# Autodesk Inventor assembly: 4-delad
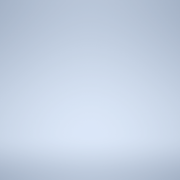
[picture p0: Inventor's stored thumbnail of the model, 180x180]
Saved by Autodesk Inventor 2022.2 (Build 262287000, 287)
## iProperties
RuleStatus: InUse
Created: 2019-06
Part Number: 4-delad
Document SubType Name: Assembly
Designer: cl
Daghöjd: 4000,000 mm
BladBredd: 987,500 mm
Fönsterbredd: 480,000 mm
Fönsterhöjd: 862,000 mm
Brösthöjd: 1070,000 mm
DagBredd: 4000,000 mm
AntalBlad: 4,000 ul
Blad2: 1012,500 mm
Blad3: 0,000 mm
Blad4: 0,000 mm
Blad5: 1012,500 mm
Blad6: 2025,000 mm
MGJ2Djup: 0,000 mm
MGJ2Bredd: 5012,500 mm
MGJ12Djup: 0,000 mm
MGJ12Bredd: 0,000 mm
MGJ56Djup: 0,000 mm
MGJ56Bredd: 0,000 mm
MGJ23Djup: 48,000 mm
MGJ23Bredd: 100,000 mm
MGJ45Djup: 48,000 mm
MGJ45Bredd: 100,000 mm
GarageRegel5: 0,000 mm
GarageRegel6: 0,000 mm
StyrskenaV: 4150,000 mm
Styrrulle2Höjd: 10,000 mm
Styrrulle2Djup: 0,000 mm
FönsterhöjdStyrning: 862,000 mm
BrösthöjdStyrning: 1070,000 mm
FönsterKarm: 54,000 mm
AndraGlasraden: 0,000 mm
BrösthöjdStyrning2: 0,000 mm
InfälldGångDörr: 0,000 ul
Infälldstyr: 845,833 mm
GångjärnHöjd: 2500,000 mm
EnDelGångDörr: 0,000 ul
VinkelJärnStyrSkena: 1456,250 mm
Author: cl
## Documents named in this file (1)
- G:\AutoCad\Carl Lund\3D-modeller systemlösningar\3D-modell-systemlösning-2022\Styrande.iam
## Named parameters: Fönsterhöjd = 862 mm, Blad2 = 1012.5 mm, Blad3 = 0, Blad4 = 0, Blad5 = 1012.5 mm, Blad6 = 2025 mm, MGJ12Djup = 0, MGJ12Bredd = 0, MGJ2Djup = 0, MGJ2Bredd = 5012.5 mm, MGJ56Djup = 0, MGJ56Bredd = 0, MGJ23Djup = 48 mm, MGJ45Djup = 48 mm, GarageRegel5 = 0, GarageRegel6 = 0, Styrrulle2Djup = 0, FönsterhöjdStyrning = 862 mm, FönsterKarm = 54 mm, AndraGlasraden = 0, BrösthöjdStyrning2 = 0.0001 mm, InfälldGångDörr = 0, Infälldstyr = 845.83333 mm, EnDelGångDörr = 0, VinkelJärnStyrSkena = 1456.25 mm
